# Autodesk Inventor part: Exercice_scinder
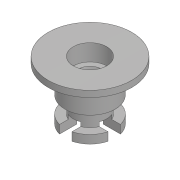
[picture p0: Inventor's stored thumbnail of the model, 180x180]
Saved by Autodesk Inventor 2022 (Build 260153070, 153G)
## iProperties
Created: 2018-06
Part Number: Exercice_scinder
Material: Plastique ABS
Document SubType Name: Modeling
Designer: Fabian Perrée
Density: 1.06 g/cm^3
Appearance: Gris clair
Author: Fabian Perrée
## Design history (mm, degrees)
sketch "Esquisse1"
  geometry: L1 (0, 0)-(0, 14); L2 (0, 14)-(10, 14); L3 (10, 14)-(10, 12.5); L4 (10, 12.5)-(6, 12.5); L5 (6, 12.5)-(6, 6); L6 (6, 6)-(4, 6); L7 (4, 6)-(4, 2); L8 (4, 2)-(6, 2); L9 (6, 2)-(6, 0); L10 (6, 0)-(0, 0); L11 (4, 14)-(4, 10); L12 (4, 10)-(2.25, 10); L13 (2.25, 10)-(2.25, 3); L14 (2.25, 3)-(0, 3)
  constraints: 28 end point, 12 perpendicular, 2 point on line, 2 vertical, 1 collinear
  dimensions: "d0" = 14 distance of L1.start L1.end; "d2" = 1.5 distance of L2.end L3.end; "d3" = 20 diameter of L3 L1; "d5" = 12 diameter of L5 L1; "d6" = 8 diameter of L7 L1; "d7" = 6.5 distance of L4.end L5.end; "d8" = 4 distance of L6.end L7.end; "d9" = 2 distance of L8.end L9.end (derived); "d10" = 8 diameter of L11 L1; "d11" = 4.5 diameter of L13 L1; "d12" = 4 distance of L11.start L11.end; "d13" = 3 distance between parallel lines of L10 L14
revolve "Révolution1" sketch "Esquisse1" stored, may be unused: angle "d14" = 90 deg
sketch "Esquisse2"
  geometry: L1 (6, 1.5)-(0, 1.5); L2 (0, 1.5)-(0, -1.5); L3 (0, -1.5)-(6, -1.5); L4 (6, -1.5)-(6, 1.5); L5 (0, 0)-(10, 0); C1 r 6 at (0, 0) reference; 1 further point
  constraints: 10 end point, 2 parallel, 1 horizontal, 1 horizontal alignment, 1 midpoint, 1 perpendicular, 1 tangent, 2 other
  dimensions: "d15" = 3 distance of L3.end L1.start
extrude "Extrusion1" cut sketch "Esquisse2" distance "d16" = 3; taper "d17" = 0 deg
pattern_circular "Réseau circulaire1" dims angle "d19" = 360 deg
chamfer "Chanfrein1" distance "d21" = 0.5; stored, may be unused: second distance "d22" = 2, angle "d23" = 45 deg
sketch "Esquisse3"
  geometry: C1 r 2.25 at (0, 0); A1 r 2.25 centre (0, 0) between (-1.5, -1.677) and (1.5, -1.677) reference
  constraints: 1 centre point, 1 coincident, 1 concentric
extrude "Extrusion2" cut sketch "Esquisse3" extent not by distance; stored distance "d24" = 10; taper "d25" = 0 deg
node "Plan de construction1"
node "Plan de construction2"
node "Solide1"
other parameters: "d26" = 5, "d27" = 0
